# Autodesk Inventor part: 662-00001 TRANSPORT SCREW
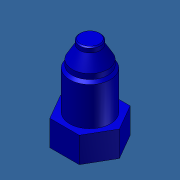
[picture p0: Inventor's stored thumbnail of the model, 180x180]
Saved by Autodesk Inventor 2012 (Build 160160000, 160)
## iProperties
Created: 2013-10
Part Number: 662-00001 TRANSPORT SCREW
Material: Steel
Document SubType Name: Modeling
Designer: Admin
Density: 7.85 g/cm^3
Mass: 5.32936 g
Surface Area: 8.25013 cm^2
Volume: 0.678899 cm^3
Author: Admin
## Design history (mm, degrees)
node "662-00001 TRANSPORT SCREW1"
node "Base1"
body "Solid1"
